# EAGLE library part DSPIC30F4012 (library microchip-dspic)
dsPIC Motion Controller DSP
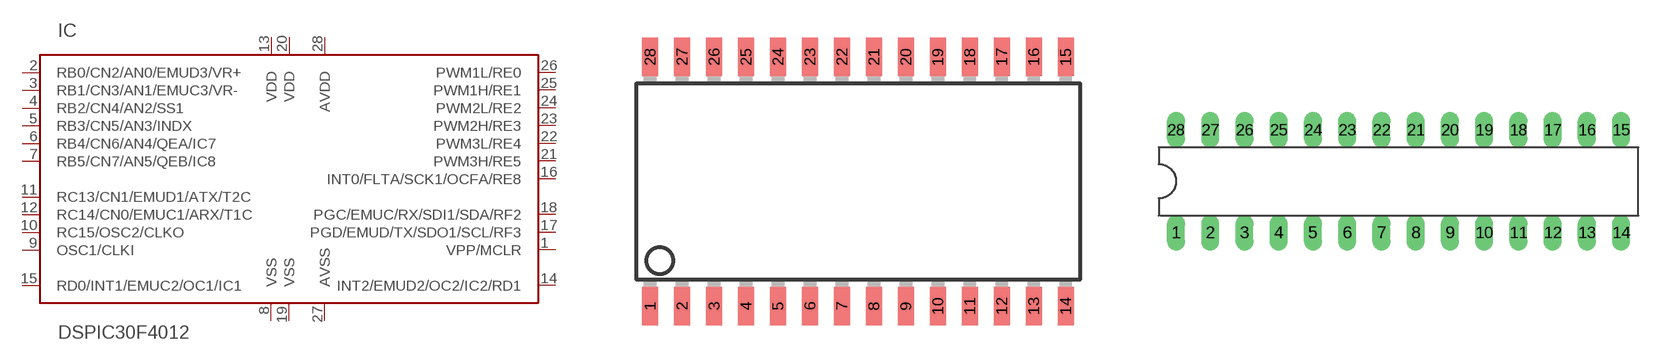
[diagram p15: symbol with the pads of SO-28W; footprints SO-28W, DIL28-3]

Designator prefix IC

## DSPIC30F4012/SO  [SO-28W]
1  VPP/MCLR  in
2  RB0/CN2/AN0/EMUD3/VR+
3  RB1/CN3/AN1/EMUC3/VR-
4  RB2/CN4/AN2/SS1
5  RB3/CN5/AN3/INDX
6  RB4/CN6/AN4/QEA/IC7
7  RB5/CN7/AN5/QEB/IC8
8  VSS  pwr
9  OSC1/CLKI  in
10  RC15/OSC2/CLKO
11  RC13/CN1/EMUD1/ATX/T2C
12  RC14/CN0/EMUC1/ARX/T1C
13  VDD  pwr
14  INT2/EMUD2/OC2/IC2/RD1
15  RD0/INT1/EMUC2/OC1/IC1
16  INT0/FLTA/SCK1/OCFA/RE8
17  PGD/EMUD/TX/SDO1/SCL/RF3
18  PGC/EMUC/RX/SDI1/SDA/RF2
19  VSS  pwr
20  VDD  pwr
21  PWM3H/RE5
22  PWM3L/RE4
23  PWM2H/RE3
24  PWM2L/RE2
25  PWM1H/RE1
26  PWM1L/RE0
27  AVSS  pwr
28  AVDD  pwr

## DSPIC30F4012/SP  [DIL28-3]
Pads as for SO-28W

## DSPIC30F4012/ML  [QFN44-8X8]
1  PGC/EMUC/RX/SDI1/SDA/RF2
6  VSS  pwr
7  VDD  pwr
9  PWM3H/RE5
10  PWM3L/RE4
11  PWM2H/RE3
12  PWM2L/RE2
14  PWM1H/RE1
15  PWM1L/RE0
16  AVSS  pwr
17  AVDD  pwr
18  VPP/MCLR  in
19  RB0/CN2/AN0/EMUD3/VR+
20  RB1/CN3/AN1/EMUC3/VR-
21  RB2/CN4/AN2/SS1
22  RB3/CN5/AN3/INDX
23  RB4/CN6/AN4/QEA/IC7
24  RB5/CN7/AN5/QEB/IC8
28  VDD  pwr
30  VSS  pwr
32  OSC1/CLKI  in
33  RC15/OSC2/CLKO
34  RC13/CN1/EMUD1/ATX/T2C
35  RC14/CN0/EMUC1/ARX/T1C
37  INT2/EMUD2/OC2/IC2/RD1
42  RD0/INT1/EMUC2/OC1/IC1
43  INT0/FLTA/SCK1/OCFA/RE8
44  PGD/EMUD/TX/SDO1/SCL/RF3

## Footprint SO-28W (pad centres in mm)
Small Outline Wide Plastic Gull Wing 300-mil body, package type SO
smd 0.635 x 1.524: 1 -7.62,-4.953; 2 -6.35,-4.953; 3 -5.08,-4.953; 4 -3.81,-4.953; 5 -2.54,-4.953; 6 -1.27,-4.953; 7 0,-4.953; 8 1.27,-4.953; 9 2.54,-4.953; 10 3.81,-4.953; 11 5.08,-4.953; 12 6.35,-4.953; 13 7.62,-4.953; 14 8.89,-4.953; 15 8.89,4.953; 16 7.62,4.953; 17 6.35,4.953; 18 5.08,4.953; 19 3.81,4.953; 20 2.54,4.953; 21 1.27,4.953; 22 0,4.953; 23 -1.27,4.953; 24 -2.54,4.953; 25 -3.81,4.953; 26 -5.08,4.953; 27 -6.35,4.953; 28 -7.62,4.953

## Footprint DIL28-3 (pad centres in mm)
Dual In Line package type P
drill 0.813 long: 1 -16.51,-3.81; 2 -13.97,-3.81; 3 -11.43,-3.81; 4 -8.89,-3.81; 5 -6.35,-3.81; 6 -3.81,-3.81; 7 -1.27,-3.81; 8 1.27,-3.81; 9 3.81,-3.81; 10 6.35,-3.81; 11 8.89,-3.81; 12 11.43,-3.81; 13 13.97,-3.81; 14 16.51,-3.81; 15 16.51,3.81; 16 13.97,3.81; 17 11.43,3.81; 18 8.89,3.81; 19 6.35,3.81; 20 3.81,3.81; 21 1.27,3.81; 22 -1.27,3.81; 23 -3.81,3.81; 24 -6.35,3.81; 25 -8.89,3.81; 26 -11.43,3.81; 27 -13.97,3.81; 28 -16.51,3.81

## Footprint QFN44-8X8 (pad centres in mm)
Quad Flat No Lead
smd 0.6 x 0.37: 1 3.825,-3.25; 2 3.825,-2.6; 3 3.825,-1.95; 4 3.825,-1.3; 5 3.825,-0.65; 6 3.825,0; 7 3.825,0.65; 8 3.825,1.3; 9 3.825,1.95; 10 3.825,2.6; 11 3.825,3.25; 23 -3.825,3.25; 24 -3.825,2.6; 25 -3.825,1.95; 26 -3.825,1.3; 27 -3.825,0.65; 28 -3.825,0; 29 -3.825,-0.65; 30 -3.825,-1.3; 31 -3.825,-1.95; 32 -3.825,-2.6; 33 -3.825,-3.25
smd 0.37 x 0.6: 12 3.25,3.825; 13 2.6,3.825; 14 1.95,3.825; 15 1.3,3.825; 16 0.65,3.825; 17 0,3.825; 18 -0.65,3.825; 19 -1.3,3.825; 20 -1.95,3.825; 21 -2.6,3.825; 22 -3.25,3.825; 34 -3.25,-3.825; 35 -2.6,-3.825; 36 -1.95,-3.825; 37 -1.3,-3.825; 38 -0.65,-3.825; 39 0,-3.825; 40 0.65,-3.825; 41 1.3,-3.825; 42 1.95,-3.825; 43 2.6,-3.825; 44 3.25,-3.825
